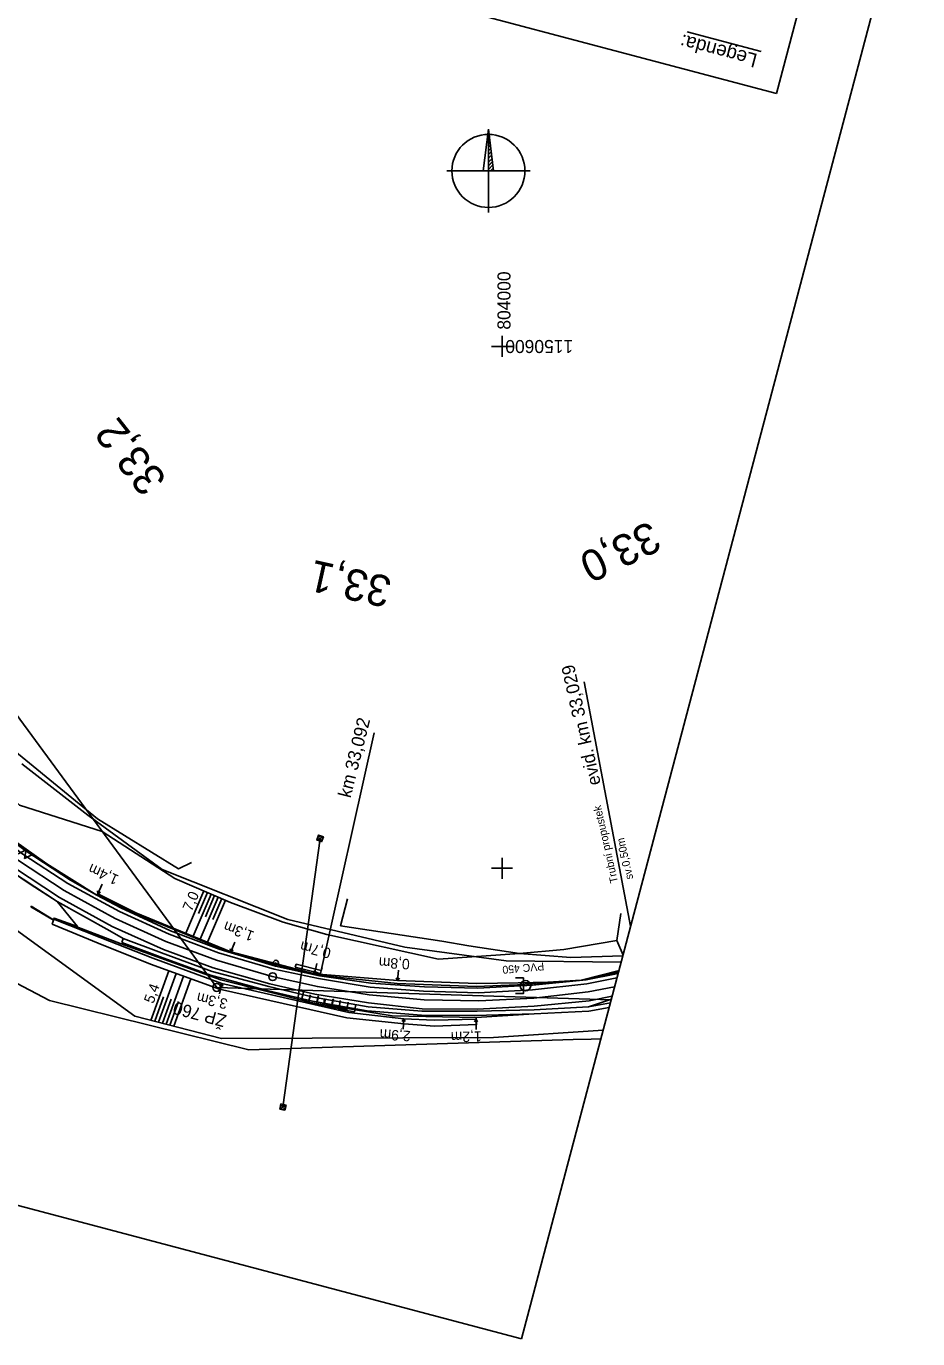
# Model space of a CAD drawing. Extents: x -805011 to -803920, y -1150790 to -1150234.
# Drawn here: x -804091.2 to -803920.3, y -1150790.1 to -1150538.7 of the extents above; entities that cross this region are included whole.
import ezdxf

# ---------------------------------------------------------------- set-up
doc = ezdxf.new("R2010")
doc.units = 0
for name, color, linetype in [('0381KM032-037P - Vrstva 1', 7, 'Continuous'), ('0381KM032-037P - Vrstva 11', 7, 'Continuous'), ('0381KM032-037P - Vrstva 13', 7, 'Continuous'), ('0381KM032-037P - Vrstva 17', 7, 'Continuous'), ('0381KM032-037P - Vrstva 19', 7, 'Continuous'), ('0381KM032-037P - Vrstva 25', 7, 'Continuous'), ('0381KM032-037P - Vrstva 4', 7, 'Continuous'), ('0381KM032-037P - Vrstva 43', 7, 'Continuous'), ('0381KM032-037P - Vrstva 44', 7, 'Continuous'), ('0381KM032-037P - Vrstva 48', 7, 'Continuous'), ('0381KM032-037P - Vrstva 49', 7, 'Continuous'), ('0381KM032-037P - Vrstva 50', 7, 'Continuous'), ('0381KM032-037P - Vrstva 7', 7, 'Continuous'), ('0381KM032-037P - Vrstva 9', 7, 'Continuous'), ('formát', 7, 'Continuous'), ('hran DP - hran DP', 7, 'Continuous'), ('krizky_1000 - souradnice', 7, 'Continuous'), ('krizky_1000 - Vrstva 1', 7, 'Continuous'), ('legenda_vyt_sit - legenda_navrh - Vrstva 7', 7, 'Continuous'), ('vyt_sit - polygon', 7, 'Continuous'), ('vyt_sit - stávající', 7, 'Continuous')]:
    doc.layers.add(name, color=color, linetype=linetype)

msp = doc.modelspace()

# ---------------------------------------------------------------- linework, layer by layer
at = {"layer": '0381KM032-037P - Vrstva 1'}
msp.add_lwpolyline([(-803978.41, -1150722.71), (-803983.51, -1150723.68), (-803993.92, -1150724.91), (-804004.46, -1150725.42), (-804014.95, -1150725.21), (-804025.47, -1150724.25), (-804035.41, -1150722.67), (-804044.08, -1150720.74), (-804054.77, -1150717.61), (-804064.47, -1150714.03), (-804074.16, -1150709.61), (-804083.95, -1150704.25), (-804092.73, -1150698.52), (-804098.22, -1150694.46), (-804106.33, -1150687.73), (-804113.82, -1150680.6), (-804121.06, -1150672.62)], dxfattribs=at)
at = {"layer": '0381KM032-037P - Vrstva 11'}
for p, q in [((-804034.26, -1150693.99), (-804035.54, -1150694.57)), ((-804034.75, -1150693.8), (-804035.36, -1150694.08)), ((-804034.44, -1150694.48), (-804035.04, -1150694.76)), ((-804041.41, -1150745.38), (-804042.6, -1150746.13)), ((-804041.93, -1150745.26), (-804042.49, -1150745.62)), ((-804041.53, -1150745.9), (-804042.08, -1150746.25))]:
    msp.add_line(p, q, dxfattribs=at)
for points in [[(-804034.6, -1150694.92), (-804035.54, -1150694.57), (-804035.19, -1150693.64), (-804034.25, -1150693.98)], [(-804041.63, -1150746.35), (-804042.61, -1150746.13), (-804042.39, -1150745.16), (-804041.41, -1150745.38)]]:
    msp.add_lwpolyline(points, close=True, dxfattribs=at)
at = {"layer": '0381KM032-037P - Vrstva 13'}
for p, q in [((-804076.66, -1150703.07), (-804077.51, -1150704.88)), ((-804090.31, -1150707.26), (-804090.39, -1150707.37)), ((-804090.39, -1150707.37), (-804086.01, -1150709.92)), ((-804086.01, -1150709.9), (-804090.31, -1150707.26)), ((-804086.01, -1150709.9), (-804085.89, -1150709.55)), ((-804086.01, -1150709.92), (-804086.01, -1150709.9)), ((-804085.98, -1150709.77), (-804085.89, -1150709.55)), ((-804051.27, -1150714.14), (-804052.03, -1150715.99)), ((-804035.82, -1150720.44), (-804051.93, -1150716.22)), ((-804035.5, -1150718.26), (-804035.97, -1150720.21)), ((-804019.87, -1150719.5), (-804020.03, -1150721.49)), ((-804054.2, -1150724.02), (-804053.75, -1150722.07)), ((-804018.95, -1150730.84), (-804018.83, -1150728.85)), ((-804004.99, -1150728.9), (-804004.87, -1150729.93)), ((-804004.95, -1150730.9), (-804004.99, -1150728.9))]:
    msp.add_line(p, q, dxfattribs=at)
for points in [[(-804077.57, -1150704.3), (-804077.51, -1150704.88), (-804077.03, -1150704.55)], [(-804052.03, -1150715.99), (-804070.24, -1150708.52), (-804077.53, -1150704.87), (-804077.68, -1150705.14), (-804070.39, -1150708.64), (-804052.3, -1150716.03), (-804051.93, -1150716.22)], [(-804085.98, -1150709.77), (-804086.01, -1150709.92), (-804086.24, -1150710.7)], [(-804004.87, -1150729.93), (-804012.98, -1150730.26), (-804018.76, -1150729.81), (-804029.79, -1150728.64), (-804054.15, -1150723.15), (-804067.44, -1150718.36), (-804077.42, -1150714.36), (-804086.24, -1150710.7)], [(-804004.99, -1150728.9), (-804013.04, -1150729.07), (-804018.83, -1150728.85), (-804029.4, -1150727.62), (-804053.75, -1150722.07), (-804066.98, -1150717.23), (-804077.05, -1150713.27), (-804085.98, -1150709.77)], [(-804085.89, -1150709.55), (-804073.05, -1150714.48), (-804053.9, -1150721.4), (-804036.64, -1150725.7), (-804021.1, -1150728.28), (-804004.99, -1150728.61), (-804004.87, -1150729.93)], [(-804072.89, -1150714.19), (-804072.63, -1150713.44), (-804065.3, -1150716.18), (-804055.61, -1150719.76), (-804044.75, -1150722.66), (-804036.16, -1150724.67), (-804025.7, -1150726.54), (-804015.38, -1150727.38), (-804004.78, -1150727.4), (-803993.85, -1150727.11), (-803983.42, -1150726.57), (-803979.23, -1150725.8)], [(-803979.45, -1150726.65), (-803983.37, -1150727.37), (-803993.84, -1150727.91), (-804005.29, -1150728.22), (-804015.43, -1150728.15), (-804025.86, -1150727.31), (-804036.32, -1150725.46), (-804045.02, -1150723.43), (-804055.91, -1150720.49), (-804065.55, -1150716.94), (-804072.89, -1150714.19)], [(-804052.11, -1150715.42), (-804052.03, -1150715.99), (-804051.56, -1150715.64)], [(-803991.2, -1150721.8), (-803996.89, -1150721.92), (-804004.84, -1150722.06), (-804020.03, -1150721.49), (-804035.97, -1150720.21), (-804052.03, -1150715.99)], [(-804036.15, -1150719.65), (-804035.97, -1150720.21), (-804035.56, -1150719.79)], [(-803991.2, -1150721.8), (-803997.06, -1150722.33), (-804004.97, -1150722.65), (-804020.12, -1150722.09), (-804035.82, -1150720.44)], [(-804020.29, -1150720.97), (-804020.03, -1150721.49), (-804019.69, -1150721.02)], [(-804053.57, -1150722.62), (-804053.75, -1150722.07), (-804054.16, -1150722.49)], [(-804018.56, -1150729.36), (-804018.83, -1150728.85), (-804019.16, -1150729.33)], [(-804004.68, -1150729.4), (-804004.99, -1150728.9), (-804005.28, -1150729.41)], [(-804004.99, -1150728.9), (-804004.99, -1150728.9), (-804004.99, -1150728.9), (-804004.99, -1150728.61)]]:
    msp.add_lwpolyline(points, dxfattribs=at)
at = {"layer": '0381KM032-037P - Vrstva 17'}
for points in [[(-804059.54, -1150698.86), (-804062.04, -1150700.07), (-804077.59, -1150690.55), (-804099.12, -1150672.95)], [(-803996.63, -1150716.3), (-804006.34, -1150714.83), (-804011.55, -1150713.97), (-804030.97, -1150711.02), (-804029.61, -1150705.83)], [(-803977.22, -1150708.65), (-803977.99, -1150713.83)], [(-803977.99, -1150713.83), (-803976.8, -1150716.64)], [(-803976.84, -1150716.79), (-803986.83, -1150717.08), (-803996.63, -1150716.3)]]:
    msp.add_lwpolyline(points, dxfattribs=at)
at = {"layer": '0381KM032-037P - Vrstva 19'}
msp.add_line((-803975.34, -1150711.1), (-803984.23, -1150664.27), dxfattribs=at)
at = {"layer": '0381KM032-037P - Vrstva 25'}
msp.add_line((-804034.9, -1150694.28), (-804042.01, -1150745.75), dxfattribs=at)
at = {"layer": '0381KM032-037P - Vrstva 4'}
for points in [[(-804073.38, -1150708.29), (-804083.27, -1150702.88), (-804091.89, -1150697.28), (-804097.27, -1150693.2), (-804105.34, -1150686.53), (-804112.64, -1150679.57), (-804120.03, -1150671.79), (-804126.35, -1150663.48), (-804132.06, -1150655.06)], [(-804073.1, -1150707.59), (-804077.68, -1150705.14), (-804082.78, -1150702.25), (-804091.44, -1150696.56), (-804096.83, -1150692.65), (-804104.73, -1150685.98), (-804112.1, -1150679.17), (-804119.6, -1150671.34), (-804125.86, -1150663.1), (-804131.6, -1150654.76)], [(-804075.18, -1150711.95), (-804085.34, -1150706.36), (-804094.07, -1150700.58), (-804099.68, -1150696.17), (-804107.82, -1150689.29), (-804115.4, -1150682.25), (-804122.72, -1150674.01), (-804129.15, -1150665.64), (-804135, -1150656.89)], [(-804074.79, -1150711.15), (-804084.84, -1150705.62), (-804093.69, -1150699.81), (-804099.23, -1150695.65), (-804107.33, -1150688.8), (-804114.94, -1150681.73), (-804122.23, -1150673.64), (-804128.61, -1150665.3), (-804134.56, -1150656.61)], [(-803977.96, -1150721), (-803983.73, -1150722.13), (-803994.13, -1150723.26), (-804004.52, -1150723.87), (-804015.05, -1150723.54), (-804025.27, -1150722.78), (-804035.17, -1150721.13), (-804043.67, -1150719.32), (-804054.39, -1150716.19), (-804063.83, -1150712.64), (-804073.38, -1150708.29)], [(-803977.73, -1150720.15), (-803983.88, -1150721.36), (-803994.18, -1150722.4), (-804004.64, -1150722.95), (-804014.86, -1150722.69), (-804025.14, -1150721.99), (-804034.98, -1150720.62), (-804043.41, -1150718.77), (-804051.93, -1150716.22), (-804054.24, -1150715.48), (-804063.6, -1150711.99), (-804073.1, -1150707.59)], [(-803978.88, -1150724.49), (-803983.32, -1150725.37), (-803993.82, -1150726.43), (-804004.8, -1150726.96), (-804015.29, -1150726.92), (-804025.6, -1150725.76), (-804035.88, -1150724.11), (-804044.5, -1150722.13), (-804055.4, -1150719.07), (-804064.95, -1150715.56), (-804074.79, -1150711.15)], [(-803979.03, -1150725.06), (-803983.42, -1150726.57), (-803993.85, -1150727.11), (-804004.78, -1150727.4), (-804015.38, -1150727.38), (-804025.7, -1150726.54), (-804036.16, -1150724.67), (-804044.75, -1150722.66), (-804055.61, -1150719.76), (-804065.3, -1150716.18), (-804072.63, -1150713.44), (-804075.18, -1150711.95)]]:
    msp.add_lwpolyline(points, dxfattribs=at)
at = {"layer": '0381KM032-037P - Vrstva 43'}
for points in [[(-803997.39, -1150721.01), (-803995.89, -1150721.01), (-803995.89, -1150724.01), (-803997.39, -1150724.01)], [(-804035.17, -1150724.55), (-804035.58, -1150726), (-804038.46, -1150725.19), (-804038.06, -1150723.74)], [(-804033.84, -1150725), (-804034.23, -1150726.45), (-804037.12, -1150725.67), (-804036.73, -1150724.22)], [(-804032.32, -1150725.04), (-804032.63, -1150726.51), (-804035.56, -1150725.9), (-804035.26, -1150724.43)], [(-804031.05, -1150725.35), (-804031.24, -1150726.84), (-804034.22, -1150726.45), (-804034.02, -1150724.96)], [(-804029.49, -1150725.62), (-804029.77, -1150727.09), (-804032.72, -1150726.52), (-804032.43, -1150725.05)], [(-804028.05, -1150726.05), (-804028.31, -1150727.53), (-804031.27, -1150727.01), (-804031.01, -1150725.53)]]:
    msp.add_lwpolyline(points, dxfattribs=at)
msp.add_circle((-803995.51, -1150722.5), 1, dxfattribs=at)
at = {"layer": '0381KM032-037P - Vrstva 44'}
msp.add_lwpolyline([(-803995.89, -1150722.51), (-803984.82, -1150721.44), (-803977.57, -1150719.55)], dxfattribs=at)
at = {"layer": '0381KM032-037P - Vrstva 48'}
for p, q in [((-804057.18, -1150704.34), (-804060.65, -1150712.45)), ((-804055.8, -1150704.93), (-804059.26, -1150713.02)), ((-804056.49, -1150704.63), (-804058.22, -1150708.69)), ((-804054.42, -1150705.52), (-804057.88, -1150713.59)), ((-804055.11, -1150705.22), (-804056.84, -1150709.27)), ((-804053.04, -1150706.11), (-804056.49, -1150714.16)), ((-804053.73, -1150705.81), (-804055.46, -1150709.84)), ((-804067.33, -1150729.13), (-804063.91, -1150719.64)), ((-804065.87, -1150729.51), (-804062.5, -1150720.14)), ((-804064.41, -1150729.89), (-804061.08, -1150720.65)), ((-804062.95, -1150730.26), (-804059.67, -1150721.16)), ((-804066.6, -1150729.32), (-804064.9, -1150724.6)), ((-804065.14, -1150729.7), (-804063.46, -1150725.05)), ((-804063.68, -1150730.07), (-804062.03, -1150725.49))]:
    msp.add_line(p, q, dxfattribs=at)
at = {"layer": '0381KM032-037P - Vrstva 49'}
msp.add_line((-804001.62, -1150732.39), (-803980.62, -1150731.04), dxfattribs=at)
for points in [[(-804216.26, -1150515.03), (-804196.49, -1150533.54), (-804188.66, -1150542.31), (-804183.72, -1150548.22), (-804177, -1150556.4), (-804165.66, -1150573.06), (-804155.49, -1150590.5), (-804146.45, -1150604.86), (-804136.37, -1150622.31), (-804131.91, -1150629.82), (-804122.71, -1150645.64), (-804115.71, -1150666.79), (-804102.89, -1150677.06), (-804092.51, -1150687.92), (-804076.71, -1150692.97), (-804062.72, -1150701.97), (-804052.08, -1150706.52)], [(-804191.88, -1150555.68), (-804187.09, -1150562.15), (-804183.47, -1150572.06), (-804177.47, -1150586.83), (-804171.32, -1150602.68), (-804162.19, -1150629.63), (-804127.41, -1150694.05), (-804117.85, -1150694.76), (-804107.49, -1150702.04), (-804103.03, -1150704.73), (-804070.42, -1150728.33), (-804053.81, -1150732.63), (-804001.62, -1150732.39)], [(-804171.89, -1150581.01), (-804161.29, -1150603.14), (-804153.71, -1150619.99), (-804149.71, -1150629.27), (-804147.81, -1150633.31), (-804145.48, -1150638.07), (-804140.73, -1150647.62), (-804139.02, -1150650.67), (-804131.55, -1150663.46), (-804125.32, -1150670.91), (-804120.07, -1150678.75), (-804110.3, -1150687.62), (-804101.36, -1150694.88), (-804099.68, -1150696.17), (-804094.07, -1150700.58), (-804090.5, -1150703.01), (-804085.34, -1150706.36), (-804081.43, -1150711.18)], [(-804115.86, -1150674.86), (-804107.6, -1150683.08), (-804103.3, -1150684.96), (-804098.16, -1150691.46), (-804087.29, -1150699.16)], [(-804087.29, -1150699.16), (-804077.68, -1150705.14), (-804077.53, -1150704.87), (-804070.24, -1150708.52), (-804052.03, -1150715.99)], [(-803977.22, -1150708.65), (-803977.99, -1150713.83), (-803988.17, -1150715.55), (-803996.63, -1150716.3), (-804012.18, -1150717.41), (-804033.61, -1150712.69), (-804041.95, -1150710.32), (-804052.08, -1150706.52)], [(-803979.45, -1150726.65), (-803983.37, -1150727.37), (-803993.84, -1150727.91), (-804004.99, -1150728.61), (-804004.87, -1150729.93), (-804012.98, -1150730.26), (-804018.76, -1150729.81), (-804029.79, -1150728.64), (-804054.15, -1150723.15), (-804067.44, -1150718.36), (-804077.42, -1150714.36), (-804086.24, -1150710.7), (-804086.01, -1150709.92)], [(-804086.01, -1150709.92), (-804086.01, -1150709.9), (-804085.89, -1150709.55), (-804081.43, -1150711.18)], [(-803984.82, -1150721.44), (-803991.2, -1150721.8), (-803996.89, -1150721.92), (-804004.84, -1150722.06), (-804020.03, -1150721.49), (-804035.97, -1150720.21), (-804052.03, -1150715.99)], [(-803984.82, -1150721.44), (-803977.66, -1150719.89)]]:
    msp.add_lwpolyline(points, dxfattribs=at)
at = {"layer": '0381KM032-037P - Vrstva 50'}
msp.add_lwpolyline([(-804090.07, -1150697.33), (-804091.56, -1150698.09), (-804091.28, -1150696.44), (-804094.26, -1150697.96), (-804093.69, -1150694.66)], dxfattribs=at)
at = {"layer": '0381KM032-037P - Vrstva 7'}
msp.add_line((-804043.32, -1150718.13), (-804043.42, -1150718.1), dxfattribs=at)
for centre, radius in [((-804043.37, -1150718.12), 0.5), ((-804043.99, -1150720.76), 0.75)]:
    msp.add_circle(centre, radius, dxfattribs=at)
at = {"layer": '0381KM032-037P - Vrstva 9'}
for p, q in [((-804034.8, -1150720.15), (-804024.5, -1150674.02)), ((-804039.51, -1150718.34), (-804039.66, -1150718.92)), ((-804039.66, -1150718.92), (-804034.81, -1150720.14)), ((-804034.66, -1150719.56), (-804039.51, -1150718.34)), ((-804034.66, -1150719.56), (-804034.52, -1150718.98)), ((-804034.81, -1150720.14), (-804034.66, -1150719.56))]:
    msp.add_line(p, q, dxfattribs=at)
at = {"layer": 'formát'}
for p, q in [((-803920.28, -1150503.02), (-803996.25, -1150790.14)), ((-804002.61, -1150558.37), (-804002.61, -1150574.37)), ((-804002.61, -1150559.01), (-804002.54, -1150558.94)), ((-804002.61, -1150559.72), (-804002.47, -1150559.57)), ((-804002.61, -1150560.42), (-804002.39, -1150560.19)), ((-804002.61, -1150561.13), (-804002.31, -1150560.82)), ((-804002.61, -1150561.84), (-804002.23, -1150561.45)), ((-804002.61, -1150562.54), (-804002.15, -1150562.08)), ((-804002.61, -1150563.25), (-804002.07, -1150562.71)), ((-804002.61, -1150563.96), (-804001.99, -1150563.34)), ((-804002.61, -1150564.67), (-804001.92, -1150563.97)), ((-804002.61, -1150565.37), (-804001.84, -1150564.59)), ((-804002.61, -1150566.08), (-804001.76, -1150565.22)), ((-804002.2, -1150566.37), (-804001.68, -1150565.85)), ((-804010.61, -1150566.37), (-803994.61, -1150566.37)), ((-803996.25, -1150790.14), (-804199.27, -1150736.42))]:
    msp.add_line(p, q, dxfattribs=at)
for points in [[(-804002.61, -1150558.37), (-804003.61, -1150566.37)], [(-804002.61, -1150558.37), (-804001.61, -1150566.37)], [(-804002.61, -1150558.37), (-804002.61, -1150566.37), (-804001.61, -1150566.37), (-804002.61, -1150558.37)]]:
    msp.add_lwpolyline(points, dxfattribs=at)
msp.add_circle((-804002.61, -1150566.37), 7, dxfattribs=at)
at = {"layer": 'hran DP - hran DP'}
for p, q in [((-804092.1, -1150680), (-804079.43, -1150689.81)), ((-804079.43, -1150689.81), (-804065.16, -1150700.21)), ((-804065.16, -1150700.21), (-804041.05, -1150709.83)), ((-804041.05, -1150709.83), (-804018.63, -1150715.09)), ((-804018.63, -1150715.09), (-803999.22, -1150717.72)), ((-804086.77, -1150725.31), (-804098.25, -1150719.35)), ((-803999.22, -1150717.72), (-803977.16, -1150717.98)), ((-804048.58, -1150734.81), (-804086.77, -1150725.31)), ((-803986.36, -1150732.8), (-804048.58, -1150734.81)), ((-803982.91, -1150732.74), (-803986.36, -1150732.8)), ((-803981.05, -1150732.7), (-803982.91, -1150732.74))]:
    msp.add_line(p, q, dxfattribs=at)
at = {"layer": 'krizky_1000 - Vrstva 1'}
for points in [[(-804000, -1150598), (-804000, -1150602)], [(-804002, -1150600), (-803998, -1150600)], [(-804000, -1150698), (-804000, -1150702)], [(-804002, -1150700), (-803998, -1150700)]]:
    msp.add_lwpolyline(points, dxfattribs=at)
at = {"layer": 'legenda_vyt_sit - legenda_navrh - Vrstva 7'}
msp.add_line((-803950.3, -1150543.47), (-803964.5, -1150539.71), dxfattribs=at)
msp.add_lwpolyline([(-803947.37, -1150551.52), (-804039.25, -1150527.21), (-804030.11, -1150492.69), (-803938.24, -1150517)], close=True, dxfattribs=at)
at = {"layer": 'vyt_sit - polygon'}
for p, q in [((-804184.81, -1150545.81), (-804054.72, -1150722.82)), ((-804054.72, -1150722.82), (-803979.07, -1150725.21))]:
    msp.add_line(p, q, dxfattribs=at)
at = {"layer": 'vyt_sit - stávající'}
msp.add_line((-804054.77, -1150722.82), (-804054.67, -1150722.82), dxfattribs=at)
msp.add_circle((-804054.72, -1150722.82), 0.756, dxfattribs=at)

# ---------------------------------------------------------------- texts
at = {"layer": '0381KM032-037P - Vrstva 13'}
for s, rotation, p in [('1,4m', 156.1294, (-804073.33, -1150701.45)), ('1,3m', 159.4135, (-804047.36, -1150712.19)), ('0,7m', 165.6438, (-804032.66, -1150715.41)), ('0,8m', 176.7126, (-804017.65, -1150717.4)), ('3,3m', 167.1636, (-804052.49, -1150725.09)), ('2,9m', 176.4791, (-804017.48, -1150731.17)), ('1,2m', 181.2027, (-804003.91, -1150731.23))]:
    msp.add_text(s, height=2, rotation=rotation, dxfattribs=at).set_placement(p)
at = {"layer": '0381KM032-037P - Vrstva 19'}
for s, height, p in [('evid. km 33,029', 2.5, (-803981.04, -1150683.82)), ('Trubní propustek', 1.5, (-803977.75, -1150702.64)), ('sv.0,50m', 1.5, (-803974.83, -1150701.98))]:
    msp.add_text(s, height=height, rotation=102.69, dxfattribs=at).set_placement(p)
at = {"layer": '0381KM032-037P - Vrstva 43'}
msp.add_text('PVC 450', height=1.5, rotation=185, dxfattribs=at).set_placement((-803991.99, -1150718.03))
at = {"layer": '0381KM032-037P - Vrstva 48'}
for s, rotation, p in [('7,0', 66.8248, (-804059.51, -1150708.39)), ('5,4', 70.2002, (-804066.86, -1150726.04))]:
    msp.add_text(s, height=2, rotation=rotation, dxfattribs=at).set_placement(p)
at = {"layer": '0381KM032-037P - Vrstva 7'}
for s, rotation, p in [('33,2', 128.139, (-804064.09, -1150625.46)), ('33,0', 205.6225, (-803971.56, -1150633.32)), ('33,1', 167.4012, (-804020.85, -1150644.28))]:
    msp.add_text(s, height=6, rotation=rotation, dxfattribs=at).set_placement(p)
at = {"layer": '0381KM032-037P - Vrstva 9'}
msp.add_text('km 33,092', height=2.5, rotation=75.8763, dxfattribs=at).set_placement((-804029.06, -1150686.64))
at = {"layer": 'krizky_1000 - souradnice'}
for s, rotation, p in [('804000', 90, (-803998.38, -1150596.79)), ('1150600', 180, (-803986.36, -1150598.77))]:
    msp.add_text(s, height=2.5, rotation=rotation, dxfattribs=at).set_placement(p)
at = {"layer": 'legenda_vyt_sit - legenda_navrh - Vrstva 7'}
msp.add_text('Legenda:', height=2.7, rotation=165.1783, dxfattribs=at).set_placement((-803950.87, -1150544.02))
at = {"layer": 'vyt_sit - stávající'}
msp.add_text('ŽP 760', height=2.4, rotation=165, dxfattribs=at).set_placement((-804052.69, -1150728.18))

doc.saveas('drawing.dxf')
